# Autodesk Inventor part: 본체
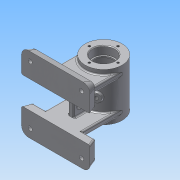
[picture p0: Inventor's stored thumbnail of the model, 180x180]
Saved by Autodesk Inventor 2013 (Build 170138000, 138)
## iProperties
Created: 2016-07
Part Number: 본체
Material: 알루미늄 6061
Document SubType Name: Modeling
Designer: Administrator
Density: 2.71 g/cm^3
Mass: 498.632 g
Surface Area: 541.48 cm^2
Volume: 183.997 cm^3
Author: Administrator
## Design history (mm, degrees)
sketch "스케치1"
  geometry: C1 r 27 at (0, 0); 1 further point
  constraints: 1 centre point, 1 coincident
  dimensions: "d0" = 54 diameter of C1
extrude "돌출1" new body sketch "스케치1" stored distance "d1" = 70; taper "d2" = 0 deg
sketch "스케치2"
  geometry: C1 r 27 at (0, 0) reference; C2 r 16 at (0, 0)
  constraints: 1 centre point, 1 coincident
  dimensions: "d3" = 32 diameter of C2
extrude "돌출2" cut sketch "스케치2" distance "d4" = 12; taper "d5" = 0 deg
sketch "스케치3"
  geometry: C1 r 16 at (0, 0) reference; C2 r 14 at (0, 0)
  constraints: 1 centre point, 1 coincident
  dimensions: "d6" = 28 diameter of C2
extrude "돌출3" cut sketch "스케치3" distance "d7" = 2; taper "d8" = 0 deg
sketch "스케치4"
  geometry: C1 r 14 at (0, 0) reference; C2 r 22 at (0, 0)
  constraints: 1 centre point, 1 coincident
  dimensions: "d9" = 44 diameter of C2
extrude "돌출4" cut sketch "스케치4" distance "d10" = 42; taper "d11" = 0 deg
sketch "스케치5"
  geometry: C1 r 27 at (0, 0) reference; C2 r 16 at (0, 0)
  constraints: 1 centre point, 1 coincident
  dimensions: "d12" = 32 diameter of C2
extrude "돌출5" cut sketch "스케치5" distance "d13" = 12; taper "d14" = 0 deg
sketch "스케치6"
  geometry: C1 r 16 at (0, 0) reference; C2 r 14 at (0, 0)
  constraints: 1 centre point, 1 coincident
  dimensions: "d15" = 28 diameter of C2
extrude "돌출6" cut sketch "스케치6" distance "d16" = 2; taper "d17" = 0 deg
node "작업 평면3"
sketch "스케치11"
  geometry: L1 (50, 20)-(-50, 20); L2 (-50, 20)-(-50, 55); L3 (-50, 55)-(50, 55); L4 (50, 55)-(50, 20); L5 (50, 20)-(-50, 55); L6 (-50, 20)-(50, 55); 3 further points
  constraints: 12 end point, 3 midpoint, 2 parallel, 1 horizontal, 1 perpendicular, 1 vertical alignment
  dimensions: "d27" = 100 distance of L2.end L3.end; "d29" = 35 distance of L1.end L2.end; "d30" = 55 distance from line of L3 point (0, 0)
extrude "돌출8" join sketch "스케치11" distance "d31" = 12; taper "d32" = 0 deg
fillet "모깎기2" dims "d33" = 10
feature "면 기울기1" dims angle "d34" = 20 deg
sketch "스케치12"
  geometry: L1 (-45.632, -45)-(-45.632, -20) reference; L2 (-45.632, -20)-(45.632, -20) reference; L3 (45.632, -20)-(45.632, -45) reference; L4 (40, -50.632)-(-40, -50.632) reference; L5 (-50, -45)-(-50, -20) reference; L6 (40, -55)-(-40, -55) reference; L7 (50, -20)-(50, -45) reference; A1 r 5.632 centre (-40, -45) between (-45.632, -45) and (-40, -50.632) reference; A2 r 5.632 centre (40, -45) between (40, -50.632) and (45.632, -45) reference; 3 further points
  dimensions: "d35" = 12.5 distance from line of L5 point (-37.5, -42.5); "d36" = 12.5 distance from line of point (-37.5, -42.5) L6; "d37" = 12.5 distance from line of L7 point (37.5, -42.5); "d38" = 12.5 distance from line of point (37.5, -42.5) L6
hole "구멍1" sketch "스케치12" at (-37.5, -42.5), (37.5, -42.5) diameter "d39" = 6; stored, may be unused: countersink angle "d43" = 90 deg, drill point angle "d45" = 0 deg; dims "d40" = 6, "d41" = 10, "d42" = 4, "d44" = 8
fillet "모깎기3" dims "d46" = 2
sketch "스케치13"
  geometry: L1 (44.232, -20)-(-44.232, -20) reference; L2 (27, -28)-(-27, -28); L3 (-27, -28)-(-27, -20); L4 (-27, -20)-(27, -20); L5 (27, -20)-(27, -28); L6 (27, -28)-(-27, -20); L7 (-27, -28)-(27, -20); 3 further points
  constraints: 12 end point, 3 midpoint, 2 parallel, 1 horizontal, 1 perpendicular, 1 point on line, 1 vertical alignment
  dimensions: "d47" = 8 distance of L2.end L3.end; "d48" = 54 distance of L3.end L4.end
extrude "돌출9" join sketch "스케치13" stored distance "d49" = 12; taper "d50" = 0 deg
node "작업 평면4"
sketch "스케치15"
  geometry: L1 (4, -25)-(-4, -25); L2 (-4, -25)-(-4, 25); L3 (-4, 25)-(4, 25); L4 (4, 25)-(4, -25); L5 (4, -25)-(-4, 25); L6 (-4, -25)-(4, 25); 2 further points
  constraints: 12 end point, 2 midpoint, 2 parallel, 1 coincident, 1 horizontal, 1 perpendicular
  dimensions: "d55" = 8 distance of L2.end L3.end; "d57" = 50 distance of L1.end L2.end
extrude "돌출10" join sketch "스케치15" distance "d58" = 22; taper "d59" = 0 deg
sketch "스케치16"
  geometry: L1 (40, 0)-(0, 0) reference; L2 (12, 13.5)-(28, 13.5); L3 (12, 6.5)-(28, 6.5); L4 (55, 63.492)-(43, 63.492) reference; L5 (43, 63.492)-(43, 61.416) reference; L6 (43, 61.416)-(41, 61.416) reference; L7 (41, 61.416)-(41, 69.633) reference; L8 (41, 69.633)-(-1, 69.633) reference; L9 (-1, 69.633)-(-1, 61.416) reference; L10 (-1, 61.416)-(-3, 61.416) reference; L11 (-3, 61.416)-(-3, 63.492) reference; L12 (-3, 63.492)-(-15, 63.492) reference; L13 (-15, 63.492)-(-15, 74.702) reference; L14 (-15, 74.702)-(55, 74.702) reference; L15 (55, 74.702)-(55, 63.492) reference; L16 (71.111, -11.316)-(75, -22) reference; L17 (75, -22)-(40, -22) reference; L18 (40, -22)-(40, 0) reference; L19 (40, 0)-(0, 0) reference; L20 (0, 21.298)-(0, 0) reference; L21 (48, -10)-(69.232, -10) reference; L22 (48, 21.298)-(48, -10) reference; L23 (55, 21.298)-(48, 21.298) reference; L24 (55, 32.508)-(55, 21.298) reference; L25 (43, 32.508)-(55, 32.508) reference; L26 (43, 34.584)-(43, 32.508) reference; L27 (41, 34.584)-(43, 34.584) reference; L28 (41, 26.367)-(41, 34.584) reference; L29 (-1, 26.367)-(41, 26.367) reference; L30 (-1, 34.584)-(-1, 26.367) reference; L31 (-3, 34.584)-(-1, 34.584) reference; L32 (-3, 32.508)-(-3, 34.584) reference; L33 (-15, 32.508)-(-3, 32.508) reference; L34 (-15, 21.298)-(-15, 32.508) reference; L35 (-8, 21.298)-(-15, 21.298) reference; L36 (-8, -10)-(-8, 21.298) reference; L37 (-29.232, -10)-(-8, -10) reference; L38 (-35, -22)-(-31.111, -11.316) reference; L39 (0, -22)-(-35, -22) reference; L40 (0, 0)-(0, -22) reference; L41 (40, 0)-(40, 21.298) reference; L42 (20, 13.5)-(20, 6.5); L43 (40, 21.298)-(0, 21.298) reference; A1 r 3.5 centre (28, 10) between (28, 6.5) and (28, 13.5); A2 r 3.5 centre (12, 10) between (12, 13.5) and (12, 6.5); A3 r 2 centre (69.232, -12) between (71.111, -11.316) and (69.232, -10) reference; A4 r 2 centre (-29.232, -12) between (-29.232, -10) and (-31.111, -11.316) reference; 1 further point
  constraints: 6 end point, 4 point on circle, 3 parallel, 3 tangent, 2 centre point, 2 midpoint
  dimensions: "d60" = 3.5 radius of A1; "d61" = 3.5 radius of A2; "d62" = 23 dimension on A1 A2; "d63" = 32 distance from line of L17 A1.centre; "d64" = 35 distance between parallel lines of L42 L13; "d65" = 8 distance from line of L42 A2.centre
extrude "돌출11" cut sketch "스케치16" stored distance "d66" = 12; taper "d67" = 0 deg
fillet "모깎기4" dims "d68" = 2
node "작업 평면6"
sketch "스케치17"
  geometry: L1 (-27, -35)-(27, -35) reference; C1 r 5 at (0, -13); 1 further point
  constraints: 1 centre point, 1 vertical alignment
  dimensions: "d71" = 5 radius of C1; "d73" = 22 distance from line of C1.centre L1
extrude "돌출12" join sketch "스케치17" stored distance "d74" = 12; taper "d75" = 0 deg
hole "구멍2" diameter "d78" = 5.188; stored, may be unused: countersink angle "d82" = 90 deg, drill point angle "d84" = 0 deg; dims "d79" = 13, "d80" = 10, "d81" = 4, "d83" = 15, "d109" = 10, "d110" = 10
node "작업 평면7"
sketch "스케치18"
  geometry: L1 (-27, -35)-(27, -35) reference; L2 (58, -49.232)-(58, -28) reference; L3 (58, -28)-(0, -28) reference; L4 (0, -28)-(0, -20) reference; L5 (0, -20)-(0, 20) reference; L6 (0, 20)-(0, 28) reference; L7 (0, 28)-(0, 35) reference; L8 (70, -55)-(59.316, -51.111) reference; L9 (70, -20)-(70, -55) reference; L10 (58, -20)-(70, -20) reference; L11 (0, -20)-(58, -20) reference; L12 (58, -28)-(58, -20) reference; L13 (0, -35)-(0, -28) reference; L14 (58, 20)-(0, 20) reference; L15 (70, 20)-(58, 20) reference; L16 (70, 55)-(70, 20) reference; L17 (59.316, 51.111)-(70, 55) reference; L18 (58, 28)-(58, 49.232) reference; L19 (0, 28)-(58, 28) reference; L20 (58, 20)-(58, 28) reference; A1 r 2 centre (60, -49.232) between (58, -49.232) and (59.316, -51.111) reference; A2 r 2 centre (60, 49.232) between (59.316, 51.111) and (58, 49.232) reference; 2 further points
  constraints: 1 other
  dimensions: "d85" = 35 distance from line of L1 point (0, 0); "d86" = 27 horizontal distance of point (0, 0) L1.start
feature "엠보싱1" sketch "스케치18" dims "d0" = 54, "d87" = 0.5, "d88" = 0
sketch "스케치19"
  geometry: L1 (0, 0)-(11.601, -20.093); L2 (0, 0)-(0, -24.439); L3 (15, -25.981)-(9.804, -28.981); L4 (9.804, -28.981)-(6.405, -23.093); L5 (6.405, -23.093)-(11.601, -20.093); L6 (11.601, -20.093)-(15, -25.981); L7 (11.601, -20.093)-(15, -25.981)
  constraints: 14 end point, 3 perpendicular, 2 parallel, 1 vertical
  dimensions: "d89" = 30 distance of L1.start L3.start; "d90" = 30 deg angle of L1 L2; "d91" = 6 distance of L3.start L3.end; "d92" = 5.88746 vertical distance of L3.end L4.end
revolve "회전1" sketch "스케치19" stored, may be unused: angle "d93" = 90 deg
hole "구멍3" diameter "d96" = 5.188; stored, may be unused: countersink angle "d100" = 90 deg, drill point angle "d102" = 0 deg; dims "d94" = 10, "d95" = 10, "d97" = 10, "d98" = 10, "d99" = 4, "d101" = 8
fillet "모깎기5" dims "d103" = 0.3, "d104" = 3
chamfer "모따기1" distance "d105" = 1; stored, may be unused: second distance "d106" = 2, angle "d107" = 45 deg
fillet "모깎기6" dims "d108" = 2
fillet "모깎기7" dims "d111" = 2
sketch "스케치20"
  geometry: C1 r 27 at (0, 0) reference; 1 further point
  constraints: 1 vertical alignment
  dimensions: "d112" = 21 distance of C1.centre point (0, 21)
sketch "스케치21"
  geometry: C1 r 27 at (0, 0) reference; 1 further point
  constraints: 1 vertical alignment
  dimensions: "d113" = 21 distance of point (0, 21) C1.centre
hole "구멍4" sketch "스케치21" at (0, 21) diameter "d114" = 3.242; stored, may be unused: countersink angle "d118" = 90 deg, drill point angle "d120" = 118 deg; dims "d115" = 8, "d116" = 10, "d117" = 4, "d119" = 10
hole "구멍5" sketch "스케치20" diameter "d121" = 3.242; stored, may be unused: countersink angle "d125" = 90 deg, drill point angle "d127" = 118 deg; dims "d122" = 8, "d123" = 10, "d124" = 4, "d126" = 10
fillet "모깎기8" dims "d131" = 2
node "솔리드1"
mirror "대칭1"
pattern_circular "원형 패턴1" dims angle "d129" = 360 deg
node "절단 모서리 투영1"
node "절단 모서리 투영2"
node "절단 모서리 투영3"
other parameters: "d54" = -48
